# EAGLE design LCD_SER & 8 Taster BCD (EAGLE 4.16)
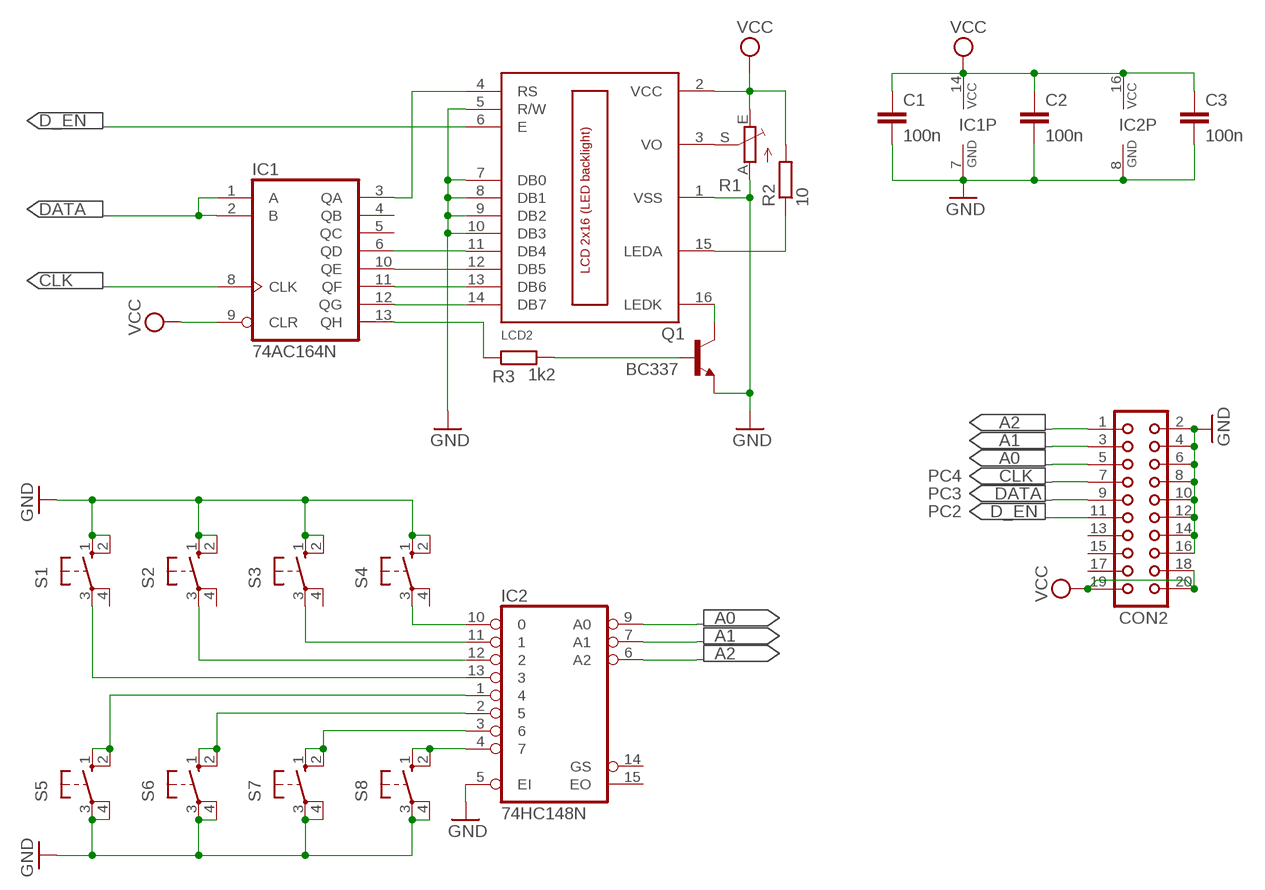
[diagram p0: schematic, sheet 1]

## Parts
C1  100n  C-EU050-025X075  [C050-025X075]
C2  100n  C-EU025-025X050  [C025-025X050]
C3  100n  C-EU050-025X075  [C050-025X075]
CON2  CON20  [CON20]
IC1  74AC164N  [DIL14]
IC2  74HC148N  [DIL16]
LCD2  LCD_2X16  [HY-1602F]
Q1  BC337  BC337-16  [TO92]
R1  TRIM_EU-PT10  [PT-10]
R2  10  R-EU_0207/12  [0207/12]
R3  1k2  R-EU_0204/7  [0204/7]
S1  10-XX  [B3F-10XX]
S2  10-XX  [B3F-10XX]
S3  10-XX  [B3F-10XX]
S4  10-XX  [B3F-10XX]
S5  10-XX  [B3F-10XX]
S6  10-XX  [B3F-10XX]
S7  10-XX  [B3F-10XX]
S8  10-XX  [B3F-10XX]

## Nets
A0: CON2.5 IC2.9(A0)
A1: CON2.3 IC2.7(A1)
A2: CON2.1 IC2.6(A2)
CLK: CON2.7 IC1.8(CLK)
D_EN: CON2.11 LCD2.6(E)
DATA: CON2.9 IC1.1(A) IC1.2(B)
GND: C1.2 C2.2 C3.2 CON2.2 CON2.4 CON2.6 CON2.8 CON2.10 CON2.12 CON2.14 CON2.16 IC1.7(GND) IC2.5(EI) IC2.8(GND) LCD2.1(VSS) LCD2.5(R/W) LCD2.7(DB0) LCD2.8(DB1) LCD2.9(DB2) LCD2.10(DB3) Q1.1(E) R1.A S1.1(S) S1.2(S1) S2.1(S) S2.2(S1) S3.1(S) S3.2(S1) S4.1(S) S4.2(S1) S5.3(P) S5.4(P1) S6.3(P) S6.4(P1) S7.3(P) S7.4(P1) S8.3(P) S8.4(P1)
N$1: IC1.6(QD) LCD2.11(DB4)
N$2: IC1.10(QE) LCD2.12(DB5)
N$3: IC1.11(QF) LCD2.13(DB6)
N$4: IC1.12(QG) LCD2.14(DB7)
N$5: LCD2.16(LEDK) Q1.3(C)
N$6: IC1.3(QA) LCD2.4(RS)
N$7: LCD2.15(LEDA) R2.1
N$8: IC1.13(QH) R3.1
N$9: LCD2.3(VO) R1.S
N$10: Q1.2(B) R3.2
N$14: IC2.13 S1.3(P)
N$15: IC2.12 S2.3(P)
N$16: IC2.10 S4.3(P)
N$17: IC2.4 S8.1(S) S8.2(S1)
N$18: IC2.11 S3.3(P)
N$19: IC2.1 S5.1(S) S5.2(S1)
N$20: IC2.2 S6.1(S) S6.2(S1)
N$21: IC2.3 S7.1(S) S7.2(S1)
VCC: C1.1 C2.1 C3.1 CON2.18 CON2.19 CON2.20 IC1.9(CLR) IC1.14(VCC) IC2.16(VCC) LCD2.2(VCC) R1.E R2.2
Unconnected: CON2.13 CON2.15 CON2.17 IC1.4(QB) IC1.5(QC) IC2.14(GS) IC2.15(EO) S1.4(P1) S2.4(P1) S3.4(P1) S4.4(P1)

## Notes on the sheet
- A2
- A1
- A0
- PC4
- PC3
- PC2
- A0
- A1
- A2

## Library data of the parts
C1-C3 = rcl:C-EU: CAPACITOR, European symbol
CON2 = con-harting:CON20: CONNECTOR
IC1 = 74xx-eu:74*164: 8-bit parallel out SHIFT REGISTER
IC2 = 74xx-eu:74*148: 10-line to 4-line and 8-line to 3-line PRIORITY ENCODER
LCD2 = lcd_2x16_led_backlight:LCD_2X16
Q1 = transistor-npn:BC337*: NPN Transistor
R1 = pot:TRIM_EU-: POTENTIOMETER
R2 R3 = rcl:R-EU_: RESISTOR, European symbol
S1-S8 = switch-omron:10-XX: OMRON SWITCH

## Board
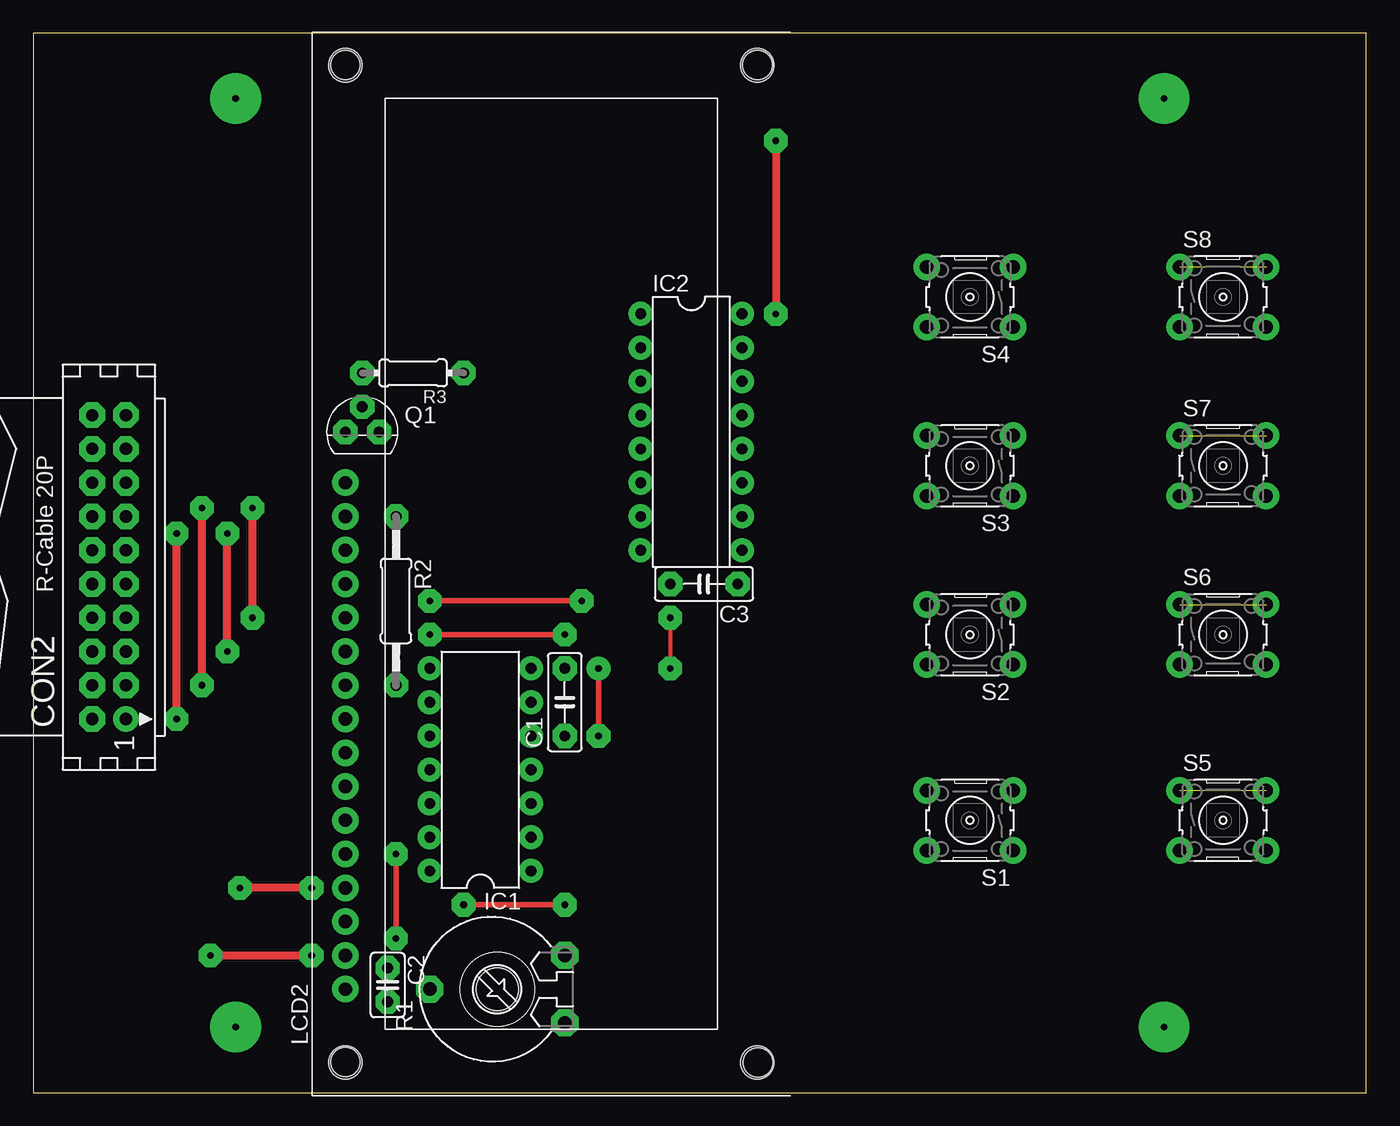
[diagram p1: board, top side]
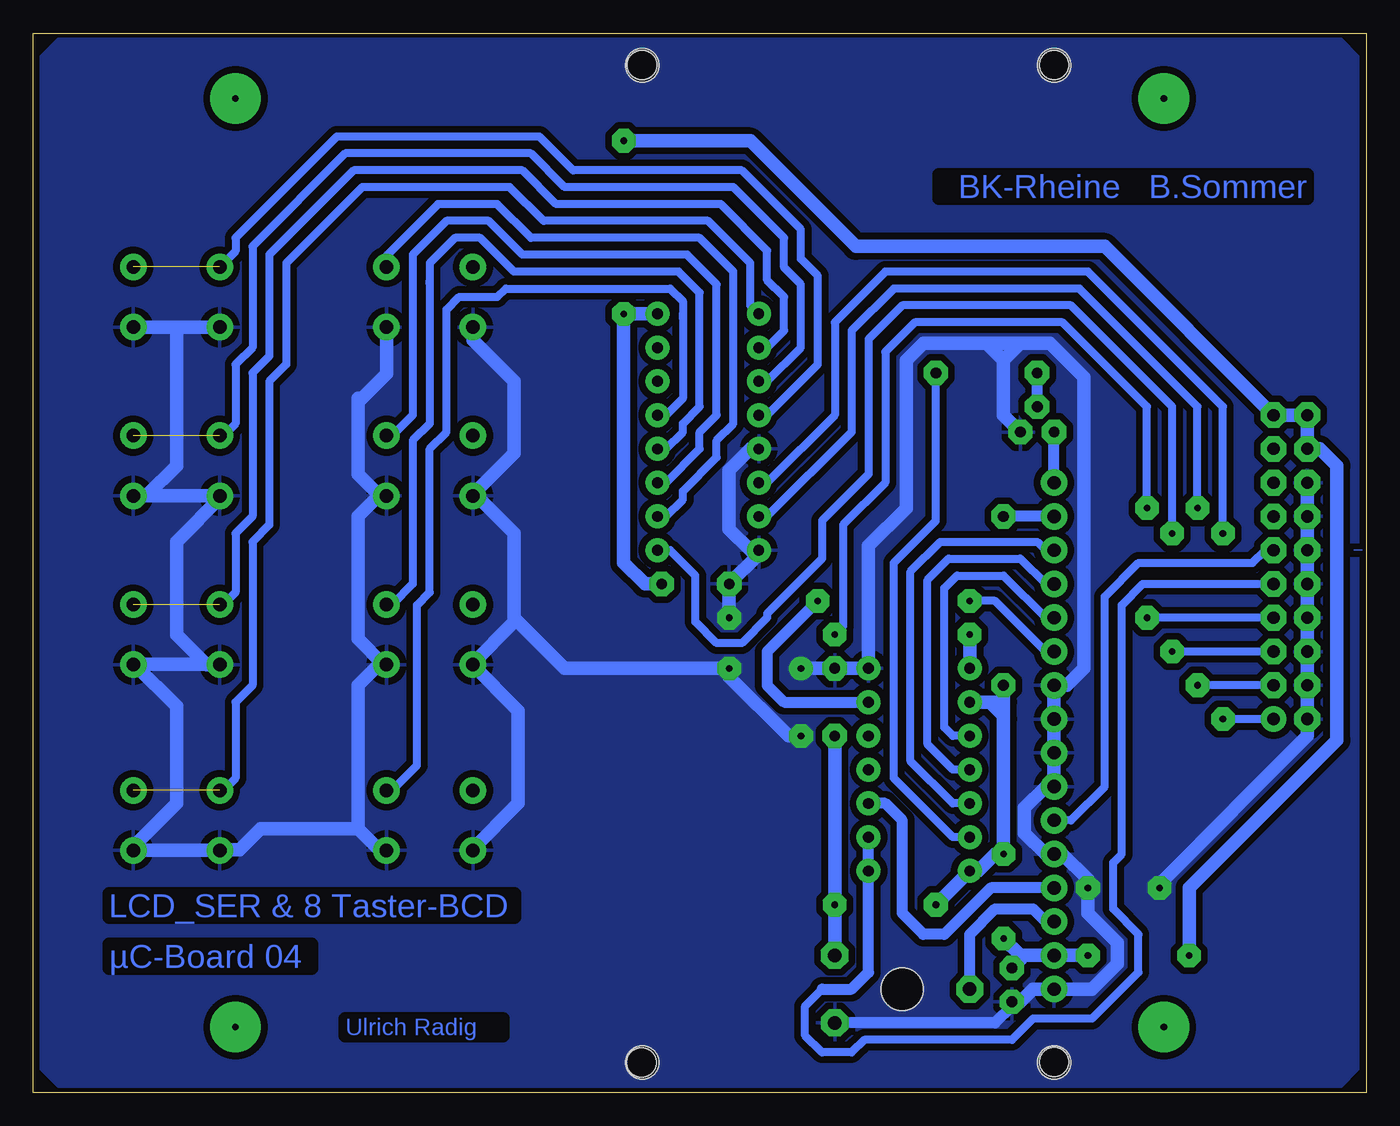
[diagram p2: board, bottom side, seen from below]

Size 100.31 x 79.68 mm. Coordinates in mm from the lower left corner, seen from the top.
Outline: 0,0 100.31,0 100.31,79.68 0,79.68 0,0
Copper layers (1*16): Top 0.035mm / dielectric 1.5mm / Bottom 0.035mm
Design rules "sommer_02_Ätzen": minimum track width 24mil, minimum drill 0.5mm, track to track 20mil, track to pad 24mil, pad to pad 20mil, via to via 20mil, smd to smd 8mil, copper to edge 0mil, drill to drill 8mil, minimum pad ring 20mil, minimum via ring 20mil, stop-mask expansion 4mil, vias tented up to drill 0mil, thermal gap 20mil
Holes 3.2 mm at 34.92,7.77
Holes 2.2 mm at 23.49,2.29 54.53,2.27 54.5,77.3 23.49,77.28

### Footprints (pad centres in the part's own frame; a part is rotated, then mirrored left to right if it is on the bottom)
C050-025X075 = drill 0.813 octagon: 1 -2.54,0; 2 2.54,0
C025-025X050 = drill 0.813 octagon: 1 -1.27,0; 2 1.27,0
CON20 = drill 0.914 round: 1 -11.43,-1.27 | drill 0.914 octagon: 2 -11.43,1.27; 3 -8.89,-1.27; 4 -8.89,1.27; 5 -6.35,-1.27; 6 -6.35,1.27; 7 -3.81,-1.27; 8 -3.81,1.27; 9 -1.27,-1.27; 10 -1.27,1.27; 11 1.27,-1.27; 12 1.27,1.27; 13 3.81,-1.27; 14 3.81,1.27; 15 6.35,-1.27; 16 6.35,1.27; 17 8.89,-1.27; 18 8.89,1.27; 19 11.43,-1.27; 20 11.43,1.27
DIL14 = drill 0.813 long: 1 -7.62,-3.81; 2 -5.08,-3.81; 3 -2.54,-3.81; 4 0,-3.81; 5 2.54,-3.81; 6 5.08,-3.81; 7 7.62,-3.81; 8 7.62,3.81; 9 5.08,3.81; 10 2.54,3.81; 11 0,3.81; 12 -2.54,3.81; 13 -5.08,3.81; 14 -7.62,3.81
DIL16 = drill 0.813 long: 1 -8.89,-3.81; 2 -6.35,-3.81; 3 -3.81,-3.81; 4 -1.27,-3.81; 5 1.27,-3.81; 6 3.81,-3.81; 7 6.35,-3.81; 8 8.89,-3.81; 9 8.89,3.81; 10 6.35,3.81; 11 3.81,3.81; 12 1.27,3.81; 13 -1.27,3.81; 14 -3.81,3.81; 15 -6.35,3.81; 16 -8.89,3.81
HY-1602F = drill 1 pad 1.93 long: 1 2.54,0; 2 5.08,0; 3 7.62,0; 4 10.16,0; 5 12.7,0; 6 15.24,0; 7 17.78,0; 8 20.32,0; 9 22.86,0; 10 25.4,0; 11 27.94,0; 12 30.48,0; 13 33.02,0; 14 35.56,0; 15 38.1,0; 16 40.64,0 | hole 2.5: -2.96,0; 72.04,0; -2.96,-31; 72.04,-31
TO92 = drill 0.813 octagon: 1 1.27,0; 2 0,1.905; 3 -1.27,0
PT-10 = drill 1.016 octagon: A -2.54,-5.08; E 2.54,-5.08; S 0,5.08
0207/12 = drill 0.813 octagon: 1 -6.35,0; 2 6.35,0
0204/7 = drill 0.813 octagon: 1 -3.81,0; 2 3.81,0
B3F-10XX = drill 1.016 long: 1 -3.251,2.261; 2 3.251,2.261; 3 -3.251,-2.261; 4 3.251,-2.261

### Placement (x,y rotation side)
C1  40,29.36 90 top
C2  26.66,8.09 270 top
C3  50.48,38.25 180 top
CON2  5.71,39.52 90 top
IC1  33.65,24.28 90 top
IC2  49.53,49.68 270 top
LCD2  23.49,5.23 90 top
Q1  24.76,49.68 0 top
R1  34.92,7.77 90 top
R2  27.3,36.98 270 top
R3  28.58,54.13 180 top
S1  70.48,20.47 180 top
S2  70.48,34.44 180 top
S3  70.48,47.14 180 top
S4  70.48,59.84 180 top
S5  89.53,20.47 0 top
S6  89.53,34.44 0 top
S7  89.53,47.14 0 top
S8  89.53,59.84 0 top

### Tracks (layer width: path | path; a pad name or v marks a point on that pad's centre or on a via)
A0  (via drill 0.5 pad 1.78)
  Top 0.61: v14.6,33.17 v14.6,42.06
  Bottom 0.61: IC2.9 52.38,40.79 50.48,38.89 50.48,35.39 48.89,33.81 46.98,33.81 45.08,35.71 45.08,36.03 40.95,40.16 40.95,43.02 37.46,46.51 37.46,56.67 34.92,59.21 22.22,59.21 14.6,51.59 v14.6,42.06 | CON2.5 v14.6,33.17
A1  (via drill 0.5 pad 1.78)
  Top 0.61: v12.7,30.63 v12.7,43.97
  Bottom 0.61: 38.73,52.22 38.73,51.59 | IC2.7 45.08,43.33 38.73,49.68 38.73,52.22 | 38.73,52.22 38.73,57.3 35.55,60.48 21.58,60.48 12.7,51.59 v12.7,43.97 | CON2.3 v12.7,30.63
A2  (via drill 0.5 pad 1.78)
  Top 0.61: v10.79,28.09 v10.79,42.06
  Bottom 0.61: IC2.6 45.08,45.87 40,50.95 40,57.94 36.19,61.75 20.95,61.75 10.79,51.59 v10.79,42.06 | CON2.1 v10.79,28.09
CLK  (via drill 0.5 pad 1.78)
  Top 0.406: v40,34.44 v29.84,34.44
  Top 0.61: v16.5,35.71 v16.5,43.97
  Bottom 0.61: v40,34.44 39.37,35.08 39.37,42.7 36.19,45.87 36.19,55.71 33.97,57.94 22.86,57.94 16.5,51.59 v16.5,43.97 | CON2.7 v16.5,35.71
  Bottom 1.016: v29.84,34.44 IC1.8
D_EN
  Bottom 0.61: LCD2.6 22.22,20.47 19.68,23.01 19.68,37.3 17.14,39.84 8.57,39.84 7.62,40.79 CON2.11
DATA
  Bottom 0.61: 40.95,7.77 42.22,6.5 42.22,4.28 40.95,3.01 38.73,3.01 37.78,3.96 26.66,3.96 25.08,5.55 20.63,5.55 17.14,9.04 17.14,11.9 19.04,13.81 19.04,17.3 18.41,17.93 18.41,36.66 16.82,38.25 CON2.9
  Bottom 0.813: IC1.2 IC1.1 37.46,9.04 38.73,7.77 40.95,7.77
GND  (via drill 0.5 pad 1.78)
  Top 0.305: v47.94,31.9 v47.94,35.71
  Top 0.406: v42.54,31.9 v42.54,26.82
  Top 0.61: v20.95,15.39 v15.55,15.39
  Bottom 0.813: R1.A 27.93,5.23 26.66,6.5 C2.2
  Bottom 1.016: C2.2 26.03,6.82 25.08,7.77 LCD2.1 20.63,7.77 18.73,9.68 18.73,11.27 20.95,13.49 v20.95,15.39 20.95,16.03 22.86,17.93 LCD2.5 24.12,17.93 25.71,19.52 25.71,21.42 24.12,23.01 LCD2.7 LCD2.8 LCD2.9 LCD2.10 22.54,30.63 21.27,31.9 21.27,53.81 23.81,56.35 26.03,56.35 | 27.3,55.08 27.3,50.95 Q1.1 | 28.57,56.35 33.33,56.35 34.6,55.08 34.6,43.97 37.46,41.11 IC1.7 C1.2 v42.54,31.9 | 27.3,55.08 28.57,56.35 | S4.1 73.73,54.05 75.72,52.06 | 75.72,52.06 75.88,51.91 | 74.25,44.88 S3.1 | 74.25,44.88 75.88,46.51 75.88,52.22 75.72,52.06 | 75.72,52.06 | 74.25,44.88 74.33,44.88 75.88,43.33 75.88,34.12 73.93,32.18 S2.1 74.33,32.18 75.88,30.63 75.88,19.84 | S1.1 74.25,18.21 75.88,19.84 | S4.2 67.23,56.59 64.13,53.49 64.13,48.09 67.3,44.92 | 67.3,44.92 67.27,44.88 S3.2 | 67.3,44.92 66.99,44.92 64.13,42.06 64.13,35.71 | 64.13,35.71 64.13,35.39 67.3,32.22 | S1.2 67.23,18.33 63.81,21.74 | 67.3,32.22 67.27,32.18 S2.2 | 63.81,21.74 63.81,28.73 67.3,32.22 | S8.4 92.74,57.58 92.7,57.62 92.67,57.58 89.53,57.58 | 89.53,57.58 S8.3 | S7.4 91.79,44.88 91.75,44.92 | 91.75,44.92 89.53,47.14 89.53,57.58 | 91.75,44.92 91.71,44.88 S7.3 86.08,44.88 | 86.08,44.88 86.04,44.92 | 86.08,44.88 89.53,41.43 89.53,34.44 87.27,32.18 S6.3 86.32,32.18 86.35,32.22 92.7,32.22 | 92.7,32.22 92.74,32.18 S6.4 | 92.7,32.22 89.53,29.04 89.53,21.74 92.78,18.49 S5.4 92.98,18.21 | 92.98,18.21 S5.3 86.08,18.21 86.04,18.25 84.77,18.25 83.18,19.84 75.88,19.84 | 92.98,18.21 93.02,18.25 | IC2.5 46.35,48.41 47.94,46.82 47.94,42.38 46.35,40.79 IC2.8 45.72,40.48 C3.2 v47.94,35.71 | CON2.16 CON2.14 CON2.12 CON2.10 CON2.8 CON2.6 CON2.4 | CON2.2 CON2.4
  Bottom 1.016: CON2.2 CON2.4 | CON2.2 4.44,26.82 15.55,15.71 v15.55,15.39 | 63.81,21.74 67.3,18.25 66.99,18.25 | 26.03,56.35 27.3,55.08 | 26.03,56.35 28.57,56.35 | 64.13,35.71 60.32,31.9 v47.94,31.9 47.94,31.27 43.49,26.82 v42.54,26.82
  pour Bottom: 1.9,79.21 0.63,77.94 0.63,1.74 1.9,0.47 98.42,0.47 99.69,1.74 99.69,77.94 98.42,79.21
N$1  (via drill 0.5 pad 1.78)
  Top 0.406: v29.84,36.98 v41.27,36.98
  Bottom 0.61: v29.84,36.98 27.93,36.98 24.12,33.17 LCD2.11
  Bottom 0.813: v41.27,36.98 45.08,33.17 45.08,30.63 43.81,29.36 IC1.6
N$2
  Bottom 0.61: IC1.10 31.11,26.82 31.74,27.46 31.74,37.94 30.79,38.89 27.3,38.89 24.12,35.71 LCD2.12
N$3
  Bottom 0.61: IC1.11 31.11,24.28 33.02,26.19 33.02,38.57 31.43,40.16 26.03,40.16 24.12,38.25 LCD2.13
N$4
  Bottom 0.61: IC1.12 31.11,21.74 34.29,24.92 34.29,39.2 32.06,41.43 24.76,41.43 24.12,40.79 LCD2.14
N$5
  Bottom 0.813: LCD2.16 Q1.3
N$6
  Bottom 0.813: IC1.3 36.19,21.74 34.92,20.47 34.92,13.49 33.33,11.9 31.74,11.9 28.25,15.39 LCD2.4
N$7
  Bottom 0.813: LCD2.15 R2.1
N$8
  Bottom 0.61: IC1.13 31.11,19.2 35.55,23.65 35.55,39.84 32.39,43 R3.1
N$9
  Bottom 0.813: LCD2.3 24.12,12.85 25.08,13.81 27.93,13.81 29.84,11.9 R1.S
N$10
  Bottom 0.813: R3.2 Q1.2
N$11
  Bottom 0: 0.31,40.79 0.95,40.79
N$12
  pour Bottom: 1.9,77.94 97.15,77.94 97.15,1.74 1.9,1.74
N$13  (via drill 0.5 pad 3.81)
  other vias: 15.24,4.92
N$14
  Bottom 0.61: IC2.13 52.7,50.95 51.43,52.22 51.43,58.25 | 51.43,58.25 51.43,58.57 | S1.3 73.3,22.73 71.43,24.6 71.43,36.66 70.48,37.62 70.48,48.41 69.21,49.68 69.21,58.89 68.26,59.84 65.4,59.84 64.77,60.48 52.38,60.48 51.43,59.52 51.43,58.25
N$15
  Bottom 0.61: IC2.12 52.7,48.41 51.43,49.68 51.43,50.32 50.16,51.59 50.16,60.16 51.75,61.75 64.13,61.75 66.67,64.29 68.57,64.29 70.48,62.38 70.48,60.8 | 70.48,60.8 70.48,50.32 71.75,49.05 71.75,38.25 73.3,36.7 S2.3 | 70.48,60.8 70.48,61.11
N$16
  Bottom 0.61: IC2.10 52.7,43.33 51.43,44.6 51.43,45.24 48.89,47.78 48.89,49.05 47.62,50.32 47.62,57.94 | 47.62,57.94 47.62,58.57 | S4.3 73.3,62.1 | 73.66,62.38 73.73,62.31 S4.3 | 73.66,62.38 73.66,62.7 | 47.62,57.94 47.62,61.75 50.16,64.29 62.86,64.29 65.4,66.83 69.84,66.83 73.66,63.02 73.66,62.38 | 73.66,62.38 73.66,62.18 S4.3
N$17  (1 unrouted)
  Bottom 0.61: S8.1 85.08,63.3 85.08,64.29 77.46,71.91 62.23,71.91 59.69,69.37 46.98,69.37 42.54,64.92 42.54,62.7 41.27,61.43 41.27,54.76 45.08,50.95 IC2.4
N$18
  Bottom 0.61: IC2.11 52.7,45.87 50.16,48.41 50.16,49.68 48.89,50.95 48.89,60.8 51.11,63.02 63.5,63.02 66.03,65.56 69.21,65.56 71.75,63.02 71.75,50.95 73.3,49.4 S3.3
N$19  (1 unrouted)
  Bottom 0.61: S5.1 86,22.73 85.08,23.65 85.08,29.36 83.81,30.63 83.81,41.43 82.55,42.7 82.55,53.49 81.27,54.76 81.27,62.38 75.56,68.1 64.45,68.1 61.91,65.56 49.53,65.56 46.35,62.38 46.35,59.21 IC2.1
N$20  (1 unrouted)
  Bottom 0.61: S6.1 86,36.7 85.08,37.62 85.08,42.06 83.81,43.33 83.81,54.13 82.55,55.4 82.55,63.02 76.19,69.37 63.5,69.37 60.96,66.83 48.57,66.83 45.08,63.34 45.08,61.11 43.81,59.84 43.81,57.3 45.08,56.03 IC2.2
N$21  (1 unrouted)
  Bottom 0.61: IC2.3 45.08,53.49 42.54,56.03 42.54,60.8 43.81,62.06 43.81,64.29 47.62,68.1 60.32,68.1 62.86,70.64 76.83,70.64 83.81,63.65 83.81,56.03 85.08,54.76 85.08,50.32 86,49.4 S7.1
N$23  (via drill 0.5 pad 3.81)
  other vias: 85.08,4.92
N$24  (via drill 0.5 pad 3.81)
  other vias: 85.08,74.77
N$25  (via drill 0.5 pad 3.81)
  other vias: 15.24,74.77
VCC  (via drill 0.5 pad 1.78)
  Top 0.406: v32.38,14.12 v40,14.12 | v27.3,11.58 v27.3,17.93
  Top 0.61: v55.88,71.59 v55.88,58.57 | v13.33,10.31 v20.95,10.31
  Bottom 0.61: 27.3,28.09 28.57,29.36
  Bottom 1.016: 26.03,10.31 LCD2.2 v20.95,10.31 | 27.3,29.36 28.57,29.36 IC1.9 | 27.3,29.36 27.3,28.09 v27.3,17.93 27.93,17.93 29.2,16.66 IC1.14 v32.38,14.12 | 27.3,29.36 R2.2 | C1.1 v40,14.12 R1.E | 26.03,10.31 v27.3,11.58 | 26.03,10.31 26.03,10 C2.1 | v55.88,71.59 46.35,71.59 38.41,63.65 19.68,63.65 CON2.19 CON2.20 CON2.18 3.49,48.41 2.22,47.14 2.22,26.5 13.33,15.39 v13.33,10.31 | 53.02,58.57 IC2.16 v55.88,58.57 55.88,39.84 54.29,38.25 C3.1

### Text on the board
Bottom: BK-Rheine B.Sommer | LCD_SER & 8 Taster-BCD | µC-Board 04 | Ulrich Radig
